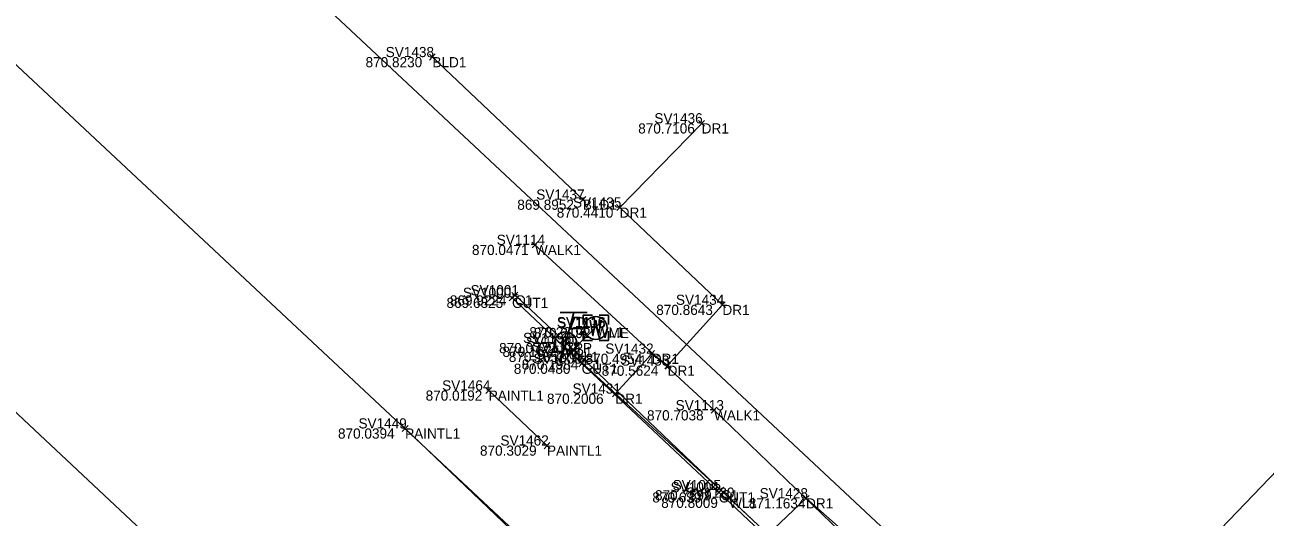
# Model space of a CAD drawing. Extents: x 1469677 to 1493262, y 375219 to 389293.
# Drawn here: x 1479985.4 to 1480132, y 379547.9 to 379606 of the extents above; entities that cross this region are included whole.
import ezdxf

# ---------------------------------------------------------------- set-up
doc = ezdxf.new("R2010")
doc.units = 0
for name, color, linetype in [('Border', 7, 'Continuous'), ('Building', 7, 'Continuous'), ('DR_X_Drive_Pipe', 7, 'Continuous'), ('DV_X_Lot_Line', 7, 'Continuous'), ('DV_X_Text', 7, 'Continuous'), ('GK_Visualization', 7, 'Continuous'), ('PNTELEV', 7, 'Continuous'), ('PNTNO', 7, 'Continuous'), ('PNTS', 7, 'Continuous'), ('RD_P_Text', 7, 'Continuous'), ('RW_P_Esmt_SW', 7, 'Continuous'), ('SV_X_Mon_Cells_Found', 7, 'Continuous'), ('SV_X_Text_Elevation', 7, 'Continuous'), ('Text Border', 7, 'Continuous')]:
    doc.layers.add(name, color=color, linetype=linetype)

msp = doc.modelspace()

# ---------------------------------------------------------------- linework, layer by layer
at = {"layer": 'Border'}
msp.add_lwpolyline([(1480051.32, 379585.39), (1480033.54, 379602.22)], dxfattribs=at)
at = {"layer": 'Building'}
for points in [[(1480047.08, 379556.35), (1480040.19, 379562.85)], [(1480030.31, 379558.37), (1480048.99, 379540.54), (1480068.18, 379522.46), (1480086.7, 379505.16), (1480104.25, 379488.61), (1480122.28, 379471.9), (1480139.96, 379455.6)]]:
    msp.add_lwpolyline(points, dxfattribs=at)
at = {"layer": 'DR_X_Drive_Pipe'}
for points in [[(1480052.86, 379570.33), (1480049.88, 379567.42)], [(1480049.15, 379568.02), (1480068.61, 379550.19), (1480086.4, 379533.42), (1480090.02, 379530.08), (1480102.3, 379519.13), (1480111.73, 379511.47), (1480120.33, 379509.14), (1480127.53, 379501.67), (1480127.91, 379496.4), (1480140.17, 379484.08), (1480149.09, 379474.71), (1480164.73, 379459.48), (1480172.62, 379452.5), (1480197.81, 379429.11)]]:
    msp.add_lwpolyline(points, dxfattribs=at)
at = {"layer": 'DV_X_Lot_Line'}
msp.add_lwpolyline([(1480215.34, 379421.05), (1480197.47, 379437.46), (1480177.8, 379455.97), (1480154.79, 379476.97), (1480132.75, 379497.48), (1480113.38, 379516.73), (1480110.75, 379519.04), (1480109.88, 379518.34), (1480091.94, 379535.27), (1480093.03, 379536.62), (1480090.22, 379539.24), (1480090.46, 379539.73), (1480084.68, 379544.88), (1480083.84, 379544.14), (1480066.82, 379560.52), (1480045.66, 379580.05)], dxfattribs=at)
at = {"layer": 'PNTELEV'}
for p, q in [((1480033.9, 379601.88), (1480033.18, 379602.57)), ((1480033.2, 379601.86), (1480033.88, 379602.59)), ((1480033.54, 379602.22), (1480033.54, 379602.22)), ((1480065, 379594.74), (1480065.71, 379594.05)), ((1480065.01, 379594.04), (1480065.7, 379594.75)), ((1480065.36, 379594.4), (1480065.36, 379594.4)), ((1480051.68, 379585.05), (1480050.95, 379585.73)), ((1480050.97, 379585.03), (1480051.66, 379585.75)), ((1480051.32, 379585.39), (1480051.32, 379585.39)), ((1480056.04, 379584.12), (1480055.31, 379584.8)), ((1480055.33, 379584.1), (1480056.02, 379584.82)), ((1480055.67, 379584.46), (1480055.67, 379584.46)), ((1480046.03, 379579.71), (1480045.29, 379580.38)), ((1480045.32, 379579.68), (1480046, 379580.41)), ((1480045.66, 379580.05), (1480045.66, 379580.05)), ((1480042.59, 379574.15), (1480043.31, 379573.46)), ((1480043.29, 379574.16), (1480042.61, 379573.44)), ((1480042.94, 379574.43), (1480043.67, 379573.75)), ((1480042.95, 379573.8), (1480042.95, 379573.8)), ((1480043.65, 379574.45), (1480042.97, 379573.72)), ((1480043.31, 379574.09), (1480043.31, 379574.09)), ((1480067.44, 379573.31), (1480068.18, 379572.64)), ((1480067.48, 379572.6), (1480068.15, 379573.34)), ((1480067.81, 379572.97), (1480067.81, 379572.97)), ((1480053.21, 379570.68), (1480052.5, 379569.98)), ((1480053.21, 379569.97), (1480052.51, 379570.69)), ((1480052.86, 379570.33), (1480052.86, 379570.33)), ((1480048.78, 379568.35), (1480049.52, 379567.68)), ((1480049.49, 379568.39), (1480048.81, 379567.65)), ((1480049.15, 379568.02), (1480049.15, 379568.02)), ((1480050.24, 379567.77), (1480049.53, 379567.07)), ((1480050.23, 379567.07), (1480049.54, 379567.78)), ((1480049.88, 379567.42), (1480049.88, 379567.42)), ((1480050.82, 379566.36), (1480051.54, 379565.67)), ((1480051.53, 379566.38), (1480050.84, 379565.65)), ((1480051.07, 379566.87), (1480051.8, 379566.19)), ((1480051.78, 379566.9), (1480051.09, 379566.17)), ((1480051.43, 379566.53), (1480051.43, 379566.53)), ((1480059.1, 379567.53), (1480059.83, 379566.86)), ((1480059.13, 379566.83), (1480059.8, 379567.57)), ((1480059.46, 379567.2), (1480059.46, 379567.2)), ((1480051.18, 379566.02), (1480051.18, 379566.02)), ((1480060.94, 379566.09), (1480061.74, 379565.49)), ((1480061.64, 379566.19), (1480061.04, 379565.39)), ((1480061.34, 379565.79), (1480061.34, 379565.79)), ((1480040.55, 379562.51), (1480039.82, 379563.2)), ((1480039.84, 379562.49), (1480040.53, 379563.22)), ((1480040.19, 379562.85), (1480040.19, 379562.85)), ((1480054.79, 379562.82), (1480055.53, 379562.15)), ((1480054.82, 379562.11), (1480055.5, 379562.85)), ((1480055.16, 379562.48), (1480055.16, 379562.48)), ((1480067.18, 379560.18), (1480066.46, 379560.87)), ((1480066.47, 379560.16), (1480067.16, 379560.88)), ((1480066.82, 379560.52), (1480066.82, 379560.52)), ((1480029.95, 379558.71), (1480030.67, 379558.02)), ((1480030.66, 379558.73), (1480029.97, 379558.01)), ((1480030.31, 379558.37), (1480030.31, 379558.37)), ((1480047.44, 379556), (1480046.71, 379556.69)), ((1480046.73, 379555.98), (1480047.42, 379556.71)), ((1480047.08, 379556.35), (1480047.08, 379556.35)), ((1480067.02, 379551.18), (1480067.75, 379550.49)), ((1480067.73, 379551.2), (1480067.04, 379550.47)), ((1480067.28, 379551.43), (1480068, 379550.74)), ((1480067.98, 379551.44), (1480067.29, 379550.72)), ((1480067.38, 379550.83), (1480067.38, 379550.83)), ((1480067.64, 379551.08), (1480067.64, 379551.08)), ((1480068.24, 379550.53), (1480068.98, 379549.86)), ((1480068.95, 379550.56), (1480068.27, 379549.82)), ((1480068.61, 379550.19), (1480068.61, 379550.19)), ((1480077.33, 379549.77), (1480078.06, 379550.46)), ((1480077.35, 379550.48), (1480078.04, 379549.75)), ((1480077.69, 379550.12), (1480077.69, 379550.12))]:
    msp.add_line(p, q, dxfattribs=at)
at = {"layer": 'PNTNO'}
msp.add_line((1480052.84, 379570.24), (1480052.84, 379570.24), dxfattribs=at)
for points in [[(1480052.44, 379571.74), (1480051.34, 379571.74), (1480051.34, 379570.64)], [(1480052.17, 379571.14), (1480052.5, 379569.34), (1480052.84, 379571.14), (1480053.17, 379569.34), (1480053.5, 379571.14)], [(1480054.34, 379570.64), (1480054.34, 379571.74), (1480053.24, 379571.74)], [(1480051.34, 379569.84), (1480051.34, 379568.74), (1480052.44, 379568.74)], [(1480053.24, 379568.74), (1480054.34, 379568.74), (1480054.34, 379569.84)]]:
    msp.add_lwpolyline(points, dxfattribs=at)
msp.add_circle((1480052.84, 379570.24), 1.35, dxfattribs=at)
at = {"layer": 'PNTS'}
for p, q in [((1480051.84, 379572.06), (1480048.64, 379572.06)), ((1480050.24, 379572.06), (1480048.64, 379566.06)), ((1480050.08, 379571.46), (1480050.93, 379571.46)), ((1480049.74, 379570.19), (1480050.93, 379570.19))]:
    msp.add_line(p, q, dxfattribs=at)
msp.add_circle((1480049.28, 379568.46), 1.3, dxfattribs=at)
msp.add_arc((1480050.95, 379570.82), 0.638, 268.8767, 91.1233, dxfattribs=at)
at = {"layer": 'RD_P_Text'}
for points in [[(1480042.95, 379573.8), (1480051.18, 379566.02), (1480067.38, 379550.83), (1480087.59, 379531.81), (1480105.07, 379515.41), (1480105.59, 379514.89), (1480115.08, 379506.3), (1480116.3, 379505.05), (1480118.53, 379502.97), (1480120.9, 379500.82), (1480138.71, 379483.7), (1480170.84, 379453.68), (1480172.57, 379452.08), (1480181.87, 379443.35), (1480182.84, 379442.22), (1480185.61, 379439.66), (1480186.49, 379438.95), (1480206.92, 379419.86)], [(1480043.31, 379574.09), (1480051.43, 379566.53), (1480067.64, 379551.08), (1480087.83, 379532.14), (1480105.19, 379515.82), (1480105.94, 379515.2), (1480115.29, 379506.59), (1480116.59, 379505.38), (1480117, 379505.56), (1480121.37, 379501.34), (1480121.05, 379501.14), (1480146.64, 379476.91), (1480171.18, 379454.1), (1480173.02, 379452.23), (1480182.18, 379443.68), (1480183.38, 379442.68), (1480186.18, 379440.01), (1480186.98, 379439.36), (1480207.41, 379420.3)]]:
    msp.add_lwpolyline(points, dxfattribs=at)
at = {"layer": 'SV_X_Mon_Cells_Found'}
msp.add_line((1480087.08, 379505.28), (1481914.32, 381407.96), dxfattribs=at)
for points in [[(1477206.54, 382340.78), (1479657.33, 379947.98), (1480466.34, 379191.88)], [(1477164.63, 382297.85), (1479615.89, 379904.59), (1480413.41, 379159.22)]]:
    msp.add_lwpolyline(points, dxfattribs=at)
at = {"layer": 'SV_X_Text_Elevation'}
msp.add_line((1479636.61, 379926.28), (1480557.83, 379065.31), dxfattribs=at)
at = {"layer": 'Text Border'}
for points in [[(1480055.16, 379562.48), (1480059.46, 379567.2), (1480061.34, 379565.79), (1480067.81, 379572.97), (1480055.67, 379584.46), (1480065.36, 379594.4)], [(1480073.14, 379545.81), (1480077.69, 379550.12), (1480090.06, 379539.2), (1480093.89, 379543.58)]]:
    msp.add_lwpolyline(points, dxfattribs=at)

# ---------------------------------------------------------------- texts
at = {"layer": 'DV_X_Text'}
for s, height, p in [('870.8230', 1.2, (1480025.64, 379601.02)), ('870.82', 0.06, (1480033.25, 379602.16)), ('870.7106', 1.2, (1480057.86, 379593.2)), ('870.71', 0.06, (1480065.09, 379594.34)), ('869.8952', 1.2, (1480043.57, 379584.19)), ('869.90', 0.06, (1480051.03, 379585.33)), ('870.4410', 1.2, (1480048.23, 379583.26)), ('870.44', 0.06, (1480055.39, 379584.4)), ('870.0471', 1.2, (1480038.21, 379578.85)), ('870.05', 0.06, (1480045.37, 379579.99)), ('869.6825', 1.2, (1480035.21, 379572.6)), ('869.9224', 1.2, (1480035.6, 379572.89)), ('869.68', 0.06, (1480042.67, 379573.74)), ('869.92', 0.06, (1480043.02, 379574.03)), ('870.8643', 1.2, (1480059.99, 379571.77)), ('870.86', 0.06, (1480067.52, 379572.91)), ('870.2204', 1.2, (1480045, 379569.13)), ('870.2192', 1.2, (1480045.53, 379569.04)), ('870.22', 0.06, (1480052.55, 379570.18)), ('870.22', 0.06, (1480052.57, 379570.27)), ('870.0772', 1.2, (1480041.42, 379567.26)), ('870.1673', 1.2, (1480041.83, 379566.82)), ('870.17', 0.06, (1480048.89, 379567.96)), ('870.08', 0.06, (1480048.99, 379568.4)), ('870.1852', 1.2, (1480042.57, 379566.22)), ('870.1984', 1.2, (1480044.1, 379565.33)), ('870.19', 0.06, (1480049.62, 379567.36)), ('870.20', 0.06, (1480051.14, 379566.47)), ('870.4954', 1.2, (1480051.65, 379566)), ('870.50', 0.06, (1480059.17, 379567.14)), ('870.0480', 1.2, (1480043.16, 379564.82)), ('870.05', 0.06, (1480050.89, 379565.96)), ('870.5624', 1.2, (1480053.55, 379564.59)), ('870.56', 0.06, (1480061.05, 379565.73)), ('870.0192', 1.2, (1480032.74, 379561.65)), ('870.02', 0.06, (1480039.9, 379562.79)), ('870.2006', 1.2, (1480047.08, 379561.28)), ('870.20', 0.06, (1480054.87, 379562.42)), ('870.7038', 1.2, (1480058.9, 379559.32)), ('870.70', 0.06, (1480066.53, 379560.46)), ('870.0394', 1.2, (1480022.38, 379557.17)), ('870.04', 0.06, (1480030.02, 379558.31)), ('870.3029', 1.2, (1480039.16, 379555.15)), ('870.30', 0.06, (1480046.79, 379556.29)), ('870.6397', 1.2, (1480059.53, 379549.63)), ('870.7599', 1.2, (1480059.84, 379549.88)), ('870.8009', 1.2, (1480060.58, 379548.99)), ('870.64', 0.06, (1480067.1, 379550.77)), ('870.76', 0.06, (1480067.35, 379551.02)), ('870.80', 0.06, (1480068.32, 379550.13)), ('871.1634', 1.2, (1480070.93, 379548.92)), ('871.16', 0.06, (1480077.46, 379550.06))]:
    msp.add_text(s, height=height, dxfattribs=at).set_placement(p)
at = {"layer": 'GK_Visualization'}
for s, p in [('BLD1', (1480033.54, 379601.02)), ('DR1', (1480065.36, 379593.2)), ('BLD1', (1480051.32, 379584.19)), ('DR1', (1480055.67, 379583.26)), ('WALK1', (1480045.66, 379578.85)), ('GUT1', (1480042.95, 379572.6)), ('C1', (1480043.31, 379572.89)), ('DR1', (1480067.81, 379571.77)), ('WME', (1480052.84, 379569.04)), ('WL1', (1480052.86, 379569.13)), ('WL1', (1480049.15, 379566.82)), ('TPP', (1480049.28, 379567.26)), ('WL1', (1480049.88, 379566.22)), ('C1', (1480051.43, 379565.33)), ('DR1', (1480059.46, 379566)), ('GUT1', (1480051.18, 379564.82)), ('DR1', (1480061.34, 379564.59)), ('PAINTL1', (1480040.19, 379561.65)), ('DR1', (1480055.16, 379561.28)), ('WALK1', (1480066.82, 379559.32)), ('PAINTL1', (1480030.31, 379557.17)), ('PAINTL1', (1480047.08, 379555.15)), ('GUT1', (1480067.38, 379549.63)), ('C1', (1480067.64, 379549.88)), ('WL1', (1480068.61, 379548.99)), ('DR1', (1480077.69, 379548.92))]:
    msp.add_text(s, height=1.2, dxfattribs=at).set_placement(p)
at = {"layer": 'RW_P_Esmt_SW'}
for s, height, p in [('SV1438', 1.2, (1480028.02, 379602.22)), ('SV1438', 0.06, (1480033.26, 379602.22)), ('SV1436', 1.2, (1480059.77, 379594.4)), ('SV1436', 0.06, (1480065.08, 379594.4)), ('SV1437', 1.2, (1480045.81, 379585.39)), ('SV1435', 1.2, (1480050.16, 379584.46)), ('SV1437', 0.06, (1480051.04, 379585.39)), ('SV1435', 0.06, (1480055.4, 379584.46)), ('SV1114', 1.2, (1480041.14, 379580.05)), ('SV1114', 0.06, (1480045.44, 379580.05)), ('SV1001', 1.2, (1480038.05, 379574.09)), ('SV1000', 1.2, (1480037.14, 379573.8)), ('SV1000', 0.06, (1480042.66, 379573.8)), ('SV1001', 0.06, (1480043.05, 379574.09)), ('SV1434', 1.2, (1480062.32, 379572.97)), ('SV1434', 0.06, (1480067.54, 379572.97)), ('SV1116', 1.2, (1480048.25, 379570.33)), ('SV1115', 1.2, (1480048.3, 379570.24)), ('SV1198', 1.2, (1480044.25, 379568.46)), ('SV1119', 1.2, (1480044.61, 379568.02)), ('SV1115', 0.06, (1480052.61, 379570.24)), ('SV1116', 0.06, (1480052.63, 379570.33)), ('SV1118', 1.2, (1480045.34, 379567.42)), ('SV1002', 1.2, (1480045.74, 379566.53)), ('SV1119', 0.06, (1480048.92, 379568.02)), ('SV1198', 0.06, (1480049.03, 379568.46)), ('SV1432', 1.2, (1480053.97, 379567.2)), ('SV1003', 1.2, (1480045.48, 379566.02)), ('SV1118', 0.06, (1480049.66, 379567.42)), ('SV1002', 0.06, (1480051.15, 379566.53)), ('SV1433', 1.2, (1480055.83, 379565.79)), ('SV1432', 0.06, (1480059.19, 379567.2)), ('SV1003', 0.06, (1480050.9, 379566.02)), ('SV1433', 0.06, (1480061.06, 379565.79)), ('SV1464', 1.2, (1480034.69, 379562.85)), ('SV1431', 1.2, (1480050.1, 379562.48)), ('SV1464', 0.06, (1480039.91, 379562.85)), ('SV1431', 0.06, (1480054.91, 379562.48)), ('SV1113', 1.2, (1480062.28, 379560.52)), ('SV1113', 0.06, (1480066.59, 379560.52)), ('SV1449', 1.2, (1480024.8, 379558.37)), ('SV1449', 0.06, (1480030.04, 379558.37)), ('SV1462', 1.2, (1480041.58, 379556.35)), ('SV1462', 0.06, (1480046.8, 379556.35)), ('SV1004', 1.2, (1480061.69, 379550.83)), ('SV1005', 1.2, (1480061.93, 379551.08)), ('SV1120', 1.2, (1480063.52, 379550.19)), ('SV1004', 0.06, (1480067.1, 379550.83)), ('SV1005', 0.06, (1480067.35, 379551.08)), ('SV1120', 0.06, (1480068.36, 379550.19)), ('SV1428', 1.2, (1480072.21, 379550.12)), ('SV1428', 0.06, (1480077.42, 379550.12))]:
    msp.add_text(s, height=height, dxfattribs=at).set_placement(p)

doc.saveas('drawing.dxf')
